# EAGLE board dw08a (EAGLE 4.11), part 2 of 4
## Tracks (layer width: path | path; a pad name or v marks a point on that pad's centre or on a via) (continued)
I_AC04  (via drill 0.61) (continued)
  Top 0.152: v105.28,40.39 105.28,35.94 105.92,35.31 105.92,30.86 B16.N2 | v109.98,49.28 110.62,48.64 v110.62,47.62 111,47.75 125.48,33.27 v125.98,33.27 | v119.38,60.33 121.41,62.36 v118.75,65.02 | v221.49,133.99 217.42,138.05 210.82,138.05 209.8,139.06 209.8,139.45 207.77,141.48 200.53,141.48 199.39,140.34 v199.01,140.08 | v232.54,141.86 233.17,141.86 v237.24,137.79 | v249.56,138.43 271.91,116.08 272.8,116.08 274.07,114.81 275.46,114.81 277.11,113.16 A03.J1 | v288.54,30.73 288.42,30.86 288.42,33.91 281.18,41.15 280.67,41.15 279.4,42.42 278.51,42.42 B03.J1 | v262.76,10.03 v267.59,10.03 | v256.67,4.32 246.51,4.32 v241.43,9.4 | v235.46,7.37 234.82,7.37 v229.87,12.32 | v226.69,9.14 224.79,9.14 208.53,25.4 207.14,25.4 206.63,25.91 203.84,25.91 199.64,30.1 197.61,30.1 v196.47,31.24 | v180.97,26.8 180.97,27.05 173.61,34.42 173.35,34.42 172.47,35.31 172.47,35.56 160.91,47.12 155.57,47.12 v149.22,53.47
  Bottom 0.152: v105.28,40.39 105.54,40.39 110.62,45.47 v110.62,47.62 | v109.98,49.28 109.98,50.93 v119.38,60.33 | v118.75,65.02 124.46,70.74 125.86,70.74 136.65,81.53 136.65,81.66 191.39,136.4 193.55,136.4 196.6,139.45 198.37,139.45 v199.01,140.08 | v221.49,133.99 221.49,134.24 229.11,141.86 v232.54,141.86 | v237.24,137.79 237.62,137.79 238.12,138.3 249.43,138.3 v249.56,138.43 | v288.54,30.73 288.29,30.73 v267.59,10.03 | v262.76,10.03 261.87,10.03 260.73,8.89 260.73,8.38 v256.67,4.32 | v241.43,9.4 241.3,9.4 239.27,7.37 v235.46,7.37 | v229.87,12.32 v226.69,9.14 | v196.47,31.24 188.09,31.24 187.07,30.23 184.4,30.23 v180.97,26.8 | v149.22,53.47 146.18,53.47 v125.98,33.27
I_AC05  (via drill 0.61)
  Top 0.152: v122.68,22.67 112.27,22.67 111.51,23.43 107.06,23.43 B16.R2 | v251.71,137.35 251.71,137.22 272.03,116.9 v272.16,116.9 | v272.16,114.36 272.16,113.6 275.72,110.05 275.72,108.9 277.5,107.12 A03.L1 | v278.38,33.97 278.13,34.23 278.13,35.75 B03.L1 | v263.65,19.24 260.1,19.24 v259.08,20.26 | v228.98,2.48 v240.41,2.48 | v226.44,1.46 220.09,1.46 219.58,0.95 217.93,0.95 210.19,8.7 209.42,8.7 208.91,9.21 208.28,9.21 175.13,42.35 175.13,43.62 174.62,44.13 173.23,44.13 v161.29,56.07
  Bottom 0.152: v122.68,22.67 147.19,47.18 153.03,47.18 161.93,56.07 | 161.93,56.07 168.53,62.67 168.53,63.31 182.75,77.53 182.75,77.66 188.47,83.38 188.72,83.38 220.73,115.38 221.23,115.38 235.97,130.11 236.47,130.11 242.44,136.08 250.44,136.08 v251.71,137.35 | v272.16,116.9 v272.16,114.36 | v278.38,33.97 278.38,32.83 274.7,29.15 273.56,29.15 v263.65,19.24 | v259.08,20.26 258.19,20.26 v240.41,2.48 | v228.98,2.48 227.46,2.48 v226.44,1.46 | 161.93,56.07 v161.29,56.07
I_AC06  (via drill 0.61)
  Top 0.152: v282.83,31.94 281.81,32.96 281.69,32.96 B03.M1 | v307.47,56.45 307.47,59.88 296.42,70.93 296.42,71.18 296.16,71.44 296.16,71.82 296.04,71.94 296.04,72.58 295.91,72.71 295.91,80.33 295.78,80.45 295.78,84.64 v287.27,93.15 | v294,100.52 292.1,100.52 289.69,102.93 | 289.69,102.93 v285.75,106.87 | v165.1,123.38 170.31,123.38 185.29,108.39 188.47,108.39 193.17,103.69 193.17,102.81 194.56,101.41 195.83,101.41 198.37,98.87 198.37,98.49 207.52,89.34 v207.52,89.22 | v263.52,134.81 265.05,134.81 280.04,119.83 280.04,118.43 282.07,116.39 282.07,113.09 289.31,105.86 289.31,105.6 289.69,105.22 289.69,102.93
  Bottom 0.152: v282.83,31.94 283.21,31.94 284.73,33.47 285.12,33.47 290.19,38.54 290.19,39.56 296.04,45.4 296.42,45.4 v307.47,56.45 | v287.27,93.15 287.27,93.79 v294,100.52 | v285.75,106.87 285.75,106.36 284.61,105.22 283.34,105.22 281.69,103.57 A03.M1 | v165.1,123.38 158.24,116.52 158.24,112.2 156.72,110.68 147.19,110.68 136.02,99.5 136.02,96.33 116.84,77.15 112.27,77.15 112.14,77.03 111.63,77.03 111.51,76.9 111.12,76.9 110.87,76.64 110.62,76.64 106.43,72.45 106.43,67.12 105.54,66.23 102.74,66.23 93.98,57.47 93.98,56.33 B17.D2 | v207.52,89.22 208.03,89.22 214.76,95.95 214.76,96.97 230.12,112.33 230.12,112.97 240.79,123.64 244.73,123.64 245.11,124.02 248.16,124.02 257.81,133.67 262.38,133.67 v263.52,134.81
I_AC07  (via drill 0.61)
  Top 0.152: v61.98,83.69 80.14,65.53 80.14,65.28 90.3,55.12 90.68,55.12 93.22,52.58 93.22,49.91 B17.F2 | v211.84,143 212.34,143 213.11,142.24 217.68,142.24 219.2,140.72 219.71,140.72 224.92,135.51 224.92,132.33 225.93,131.32 225.93,131.19 226.06,131.19 226.06,131.06 226.19,131.06 226.19,130.94 226.31,130.94 226.31,130.81 226.44,130.81 226.44,130.68 228.98,130.68 229.87,129.79 230.63,129.79 231.27,129.16 231.27,128.65 v231.78,128.14 | v267.72,138.18 v295.78,110.11 | v283.59,96.9 281.69,96.9 A03.P1 | v285.24,22.23 285.24,24.38 283.08,26.54 281.69,26.54 B03.P1 | v267.33,4.83 264.16,4.83 261.24,7.75 260.99,7.75 259.71,9.02 252.86,9.02 240.54,21.34 240.54,21.46 239.27,22.73 239.14,22.73 235.46,26.42 235.46,28.45 v234.7,29.21 | v243.97,38.1 243.46,38.1 243.08,38.48 242.57,38.48 242.44,38.61 242.32,38.61 242.32,38.73 242.19,38.73 242.19,38.86 242.06,38.86 242.06,38.99 241.94,38.99 241.94,39.12 241.81,39.12 241.81,39.24 239.27,41.78 239.14,41.78 239.14,41.91 239.01,41.91 239.01,42.04 238.89,42.04 238.89,42.16 238.76,42.16 238.76,42.29 238.63,42.29 238.63,42.42 236.09,44.96 235.97,44.96 235.97,45.09 235.84,45.09 235.84,45.21 235.71,45.21 235.71,45.34 235.59,45.34 235.59,45.47 235.46,45.47 235.46,45.59 232.92,48.13 232.79,48.13 232.79,48.26 232.66,48.26 232.66,48.39 232.54,48.39 232.54,48.51 232.41,48.51 232.41,48.64 232.28,48.64 232.28,48.77 229.74,51.31 229.62,51.31 229.62,51.44 229.49,51.44 229.49,51.56 229.36,51.56 229.36,51.69 229.24,51.69 229.24,51.82 229.11,51.82 229.11,55.12 224.41,59.82 221.74,59.82 221.36,60.2 217.81,60.2 v213.23,64.77
  Top 0.152: v200.03,54.48 200.03,54.99 190.63,64.39 190.63,65.28 188.59,67.31 188.21,67.31 171.96,83.57 171.96,84.84 v171.7,85.09 | v105.54,27.69 104.52,27.69 v87.76,44.45
  Bottom 0.152: v61.98,83.69 62.48,83.69 92.96,114.17 106.17,114.17 128.02,136.02 130.56,136.02 133.1,138.56 139.06,138.56 141.1,140.59 163.58,140.59 165.61,142.62 187.2,142.62 187.58,143 v211.84,143 | v231.78,128.14 231.78,128.65 233.81,130.68 233.93,130.68 237.36,134.11 239.4,134.11 242.06,136.78 246.25,136.78 247.14,137.67 250.95,137.67 251.46,138.18 v267.72,138.18 | v295.78,110.11 295.78,109.09 v283.59,96.9 | v285.24,22.23 284.73,22.23 v267.33,4.83 | v234.7,29.21 235.08,29.21 v243.97,38.1 | v213.23,64.77 213.23,64.64 204.98,56.39 204.6,56.39 203.71,55.5 203.2,55.5 202.18,54.48 v200.03,54.48 | v171.7,85.09 169.29,85.09 164.08,79.88 160.78,79.88 149.22,68.33 148.34,68.33 147.19,67.18 146.69,67.18 110.49,30.99 108.84,30.99 v105.54,27.69 | v87.76,44.45 87.76,44.96 89.92,47.12 91.31,47.12 92.96,48.77 B17.F2
I_AC08  (via drill 0.61)
  Top 0.152: v108.46,57.47 110.74,57.47 111.38,56.83 113.54,56.83 115.32,55.05 115.7,55.05 118.36,52.39 119.13,52.39 141.6,29.91 | 141.6,29.91 151.89,19.62 152.4,19.62 153.92,18.1 154.43,18.1 162.94,9.59 165.35,9.59 171.96,2.98 173.74,2.98 174.12,2.6 175.64,2.6 v176.78,1.46 | v206.38,25.08 208.28,25.08 221.74,11.62 221.74,10.35 224.79,7.3 227.71,7.3 v230.76,4.25 | v246.38,19.37 247.01,19.37 253.49,12.89 255.4,12.89 258.32,9.97 259.46,9.97 259.71,9.72 261.49,9.72 v264.41,6.79 | v256.29,113.6 271.91,97.98 275.08,97.98 280.67,92.39 280.67,91.25 A03.S1 | v254.89,112.33 254.38,112.33 252.86,113.86 252.6,113.86 252.22,114.24 252.22,114.75 229.74,137.22 229.11,137.22 v224.92,141.41 | v222.25,139.89 221.11,139.89 v219.46,141.54 | v196.85,117.79 196.85,115.89 211.71,101.03 v211.84,101.03 | 141.6,29.91 v141.73,29.91
  Bottom 0.152: v108.46,57.47 107.44,56.45 107.44,55.05 95.63,43.24 94.36,43.24 B17.J2 | v176.78,1.46 182.12,1.46 182.88,2.22 183.51,2.22 v206.38,25.08 | v230.76,4.25 231.01,4.25 237.11,10.35 237.36,10.35 v246.38,19.37 | v264.41,6.79 265.56,6.79 277.37,18.61 279.15,18.61 280.54,20 B03.S1 | v256.29,113.6 256.16,113.6 v254.89,112.33 | v224.92,141.41 223.77,141.41 v222.25,139.89 | v219.46,141.54 216.41,141.54 215.39,140.53 215.14,140.53 202.31,127.7 202.31,126.3 203.84,124.78 v196.85,117.79 | v211.84,101.03 211.84,100.27 207.65,96.08 207.01,96.08 199.14,88.2 199.14,86.68 189.48,77.03 188.85,77.03 v141.73,29.91
I_AC09  (via drill 0.61)
  Top 0.152: v275.34,49.4 272.29,52.45 272.29,53.59 271.91,53.98 271.91,54.86 B03.D2 | v257.43,31.5 257.43,29.84 v259.33,27.94 | v238.89,8.13 237.87,8.13 234.44,11.56 234.44,11.68 230.76,15.37 227.84,15.37 227.71,15.49 227.08,15.49 217.93,24.64 217.93,24.89 213.23,29.59 213.23,31.75 v213.11,31.88 | v213.23,33.91 212.72,33.91 210.95,35.69 210.44,35.69 208.53,37.59 v206.38,37.59 | v204.85,36.07 195.58,45.34 193.68,45.34 v192.91,44.58 | v169.8,25.53 v156.08,39.24 | v124.97,13.97 124.21,13.97 122.81,15.37 111.63,15.37 v94.11,32.89 | v262.25,132.08 268.48,125.86 270.76,125.86 A03.D2 | v244.47,114.81 244.47,115.32 243.97,115.82 243.97,116.46 243.84,116.46 243.84,116.59 243.71,116.59 243.71,116.71 243.59,116.71 243.59,116.84 243.46,116.84 243.46,116.97 243.33,116.97 240.79,119.51 240.79,119.63 240.66,119.63 240.66,119.76 240.54,119.76 240.54,119.89 240.41,119.89 240.41,120.02 240.28,120.02 240.28,120.14 240.16,120.14 237.62,122.68 237.62,122.81 237.49,122.81 237.49,122.94 237.36,122.94 237.36,123.06 237.24,123.06 237.24,123.19 237.11,123.19 237.11,123.32 236.98,123.32 235.84,124.46 235.84,124.59 233.93,126.49 231.78,126.49 230.89,127.38 228.22,127.38 225.43,130.18 222.63,130.18 222.12,130.68 220.09,130.68 214.63,136.14 212.98,136.14 211.58,137.54 210.57,137.54 v209.04,139.06 | v196.22,129.92 194.56,129.92 v193.55,130.94 | v152.91,93.09 152.91,89.92 162.94,79.88 165.99,79.88 167,78.87 167,76.2 170.43,72.77 170.43,72.39 201.04,41.78 203.2,41.78 v203.84,41.15
  Bottom 0.152: v257.43,31.5 v275.34,49.4 | v259.33,27.94 258.7,27.94 v238.89,8.13 | v213.11,31.88 213.11,33.78 v213.23,33.91 | v204.85,36.07 v206.38,37.59 206.63,37.97 207.01,38.35 207.01,39.12 204.98,41.15 v203.84,41.15 | v192.91,44.58 192.28,44.58 186.31,38.61 182.88,38.61 v169.8,25.53 | v156.08,39.24 150.5,33.66 150.5,33.4 146.94,29.84 146.94,29.59 131.7,14.35 130.18,14.35 127.76,16.76 v124.97,13.97 | v94.11,32.89 94.11,35.81 B17.L2 | v262.25,132.08 260.73,132.08 259.33,130.68 256.03,130.68 254.51,129.16 254.51,124.97 244.47,114.94 v244.47,114.81 | v209.04,139.06 207.26,139.06 200.53,132.33 200.53,131.7 199.52,130.68 196.98,130.68 v196.22,129.92 | v193.55,130.94 191.77,130.94 175.39,114.55 174.88,114.55 165.48,105.16 164.97,105.16 v152.91,93.09
I_AC10  (via drill 0.61)
  Top 0.152: v116.97,50.93 119.63,50.93 v151.76,18.8 | v186.69,17.02 174.62,29.08 169.29,29.08 167.89,30.48 167.51,30.48 166.88,31.11 v166.5,31.11 166.75,31.5 167.64,32.38 v168.78,32.38 | v197.87,24.89 198.37,24.89 200.91,22.35 201.42,22.35 210.57,13.21 215.14,13.21 216.03,12.32 217.81,12.32 v222.38,7.75 | v250.82,30.35 250.82,30.1 251.84,29.08 v253.87,29.08 | v253.24,139.95 270.51,122.68 273.94,122.68 A03.E2 | v217.55,119.51 217.55,119.25 v225.17,111.63 | v208.91,98.55 v211.96,98.55 | v194.56,83.57 194.82,83.57 196.72,81.66 196.72,80.64 v205.1,72.26 | v205.1,67.06 205.1,66.42 v206.38,65.15
  Bottom 0.152: v116.97,50.93 96.65,30.61 94.36,30.61 B17.N2 | v151.76,18.8 154.18,18.8 v166.5,31.11 | v186.69,17.02 186.82,17.02 194.69,24.89 v197.87,24.89 | v222.38,7.75 226.44,7.75 237.24,18.54 239.14,18.54 242.32,21.72 242.57,21.72 243.59,22.73 243.59,23.11 v250.82,30.35 | v253.87,29.08 261.75,36.96 261.87,36.96 262.38,37.47 262.38,37.97 268.35,43.94 268.35,44.45 272.54,48.64 272.54,50.04 274.19,51.69 B03.E2 | v253.24,139.95 249.3,139.95 246.13,143.13 239.52,143.13 236.73,140.34 236.73,139.83 224.41,127.51 223.27,127.51 222.88,127.13 222.88,124.84 v217.55,119.51 | v225.17,111.63 225.17,109.86 224.92,109.6 224.92,108.97 224.79,108.97 224.79,108.84 224.66,108.84 224.66,108.71 224.54,108.71 224.54,108.58 224.41,108.58 224.41,108.46 224.28,108.46 221.74,105.92 221.74,105.79 221.62,105.79 221.62,105.66 221.49,105.66 221.49,105.54 221.36,105.54 221.36,105.41 221.23,105.41 221.23,105.28 221.11,105.28 218.57,102.74 218.57,102.62 214.88,98.93 212.34,98.93 v211.96,98.55 | v208.91,98.55 198.75,88.39 198.75,87.76 v194.56,83.57 | v205.1,67.06 v205.1,72.26 | v206.38,65.15 206.38,65.02 205.36,64.01 202.69,64.01 202.56,63.88 201.17,63.88 186.94,49.66 186.06,49.66 v168.78,32.38
I_AC11  (via drill 0.61)
  Top 0.152: v101.6,17.21 101.09,17.72 101.09,17.97 95.63,23.43 94.36,23.43 B17.R2 | v205.49,111.82 206.5,111.82 v213.11,105.22 | v252.98,137.1 255.52,137.1 274.07,118.56 274.07,116.9 274.32,116.65 A03.H2 275.34,115.51 276.99,113.86 278.26,113.86 279.65,112.46 279.65,110.68 279.91,110.43 279.91,109.03 285.62,103.31 285.62,102.42 304.42,83.63 v304.42,82.61 | v281.05,38.04 274.95,44.13 274.95,45.28 B03.H2 | v289.94,46.93 289.94,46.29 294.13,42.1 294.77,42.1 298.7,38.16 298.7,36.89 v298.83,36.77 | v308.86,50.61 308.86,61.02 305.31,64.58 305.31,73.72 v304.42,74.61
  Bottom 0.152: v101.6,17.21 101.98,17.21 161.42,76.64 161.67,76.64 161.93,76.9 162.31,76.9 162.43,77.03 162.94,77.03 163.07,77.15 173.99,77.15 177.29,80.45 177.29,83.63 194.82,101.16 195.07,101.16 195.71,101.79 195.71,102.04 v205.49,111.82 | v213.11,105.22 214.76,105.22 217.93,108.39 219.07,108.39 229.24,118.56 230.5,118.56 233.81,121.86 234.06,121.86 239.14,126.94 242.82,126.94 v252.98,137.1 | v289.94,46.93 v281.05,38.04 | v298.83,36.77 299.72,36.77 300.36,37.4 300.36,37.91 304.67,42.23 304.67,46.42 v308.86,50.61 | v304.42,82.61 v304.42,74.61
I_ACCEPT  (via drill 0.61)
  Top 0.152: v241.05,7.18 227.97,20.26 224.54,20.26 B07.S2 223.14,21.02 222.63,21.53 | v259.84,22.42 260.1,22.42 261.37,21.14 B04.S2 | v144.53,66.74 144.53,66.61 156.72,54.42 162.05,54.42 v208.41,8.06 | v222.12,21.65 222.5,21.65 222.63,21.53 | v242.82,60.77 v236.85,66.74 | v216.41,31.56 222.63,25.34 222.63,21.53
  Bottom 0.152: v241.05,7.18 244.6,7.18 v259.84,22.42 | v144.53,66.74 134.87,57.09 134.37,57.09 132.84,55.56 132.84,55.05 130.05,52.26 130.05,51.75 124.71,46.42 122.94,46.42 B15.H2 | v208.41,8.06 208.53,8.06 v222.12,21.65 | v236.85,66.74 237.36,67.25 237.36,68.52 256.29,87.44 256.29,87.82 258.57,90.11 261.24,90.11 A04.S2 | v242.82,60.77 228.22,46.16 227.58,46.16 217.81,36.39 217.81,35.24 216.41,33.85 v216.41,31.56
I_ACCLR  (via drill 0.61)
  Top 0.152: v281.05,25.34 279.78,26.61 275.34,26.61 B03.P2 | v290.96,34.23 290.96,34.48 289.43,36.01 v289.43,38.92 | v303.78,53.91 303.28,53.91 292.61,64.58 292.61,68.64 v292.23,69.03 | v294.64,73.72 294.64,78.42 290.96,82.11 287.78,82.11 276.73,93.15 276.73,95.06 275.34,96.46 A03.P2 | v130.18,9.97 121.41,18.73 115.19,18.73 114.81,19.11 108.97,19.11 85.6,42.48 81.66,42.48 B18.J2 | v155.32,31.56 158.12,31.56 168.28,21.4 168.91,21.4 173.99,16.32 174.24,16.32 181.23,9.34 185.29,9.34 188.72,5.91 193.29,5.91 193.68,5.52 195.2,5.52 v197.99,2.73 | v215.9,9.08 218.82,9.08 v224.41,3.49 | v228.85,7.3 231.9,7.3 235.97,3.24 242.95,3.24 v243.46,2.73
  Bottom 0.152: 281.81,25.34 282.07,25.34 v290.96,34.23 | 281.81,25.34 v281.05,25.34 | v289.43,38.92 289.43,39.56 v303.78,53.91 | v292.23,69.03 292.23,71.31 v294.64,73.72 | v130.18,9.97 133.73,9.97 v155.32,31.56 | v197.99,2.73 208.53,2.73 208.79,2.98 209.8,2.98 v215.9,9.08 | v224.41,3.49 225.04,3.49 v228.85,7.3 | v243.46,2.73 259.21,2.73 281.81,25.34
I_ADD00  (via drill 0.61)
  Top 0.152: v71.75,37.78 55.88,53.66 55.88,54.8 B20.D2 | v146.81,99.25 148.97,99.25 v169.93,78.3 | v226.82,133.67 228.73,133.67 v246.51,115.89 246.76,115.51 v252.98,109.28 | v253.62,72.45 260.86,65.22 260.86,64.58 263.14,62.29 264.41,62.29 B04.B1 | v253.62,79.44 253.62,83.25 252.09,84.77 251.46,84.77 241.81,94.42 241.81,95.19 v240.16,96.84
  Bottom 0.152: v71.75,37.78 78.36,37.78 98.04,57.47 99.82,57.47 108.97,66.61 110.62,66.61 112.27,68.26 115.19,68.26 118.62,71.69 119.25,71.69 135.25,87.69 135.51,87.69 139.32,91.5 139.32,91.76 v146.81,99.25 | v169.93,78.3 174.5,82.87 175.13,82.87 192.15,99.89 192.15,100.52 194.56,102.93 195.33,102.93 205.99,113.6 206.76,113.6 v226.82,133.67 | v246.51,115.89 246.76,115.89 252.35,121.47 252.35,121.6 252.73,121.98 253.75,121.98 261.49,129.73 262.76,129.73 264.41,131.38 A04.B1 | v253.62,79.44 v253.62,72.45 | v240.16,96.84 240.54,96.84 v252.98,109.28
I_ADD01  (via drill 0.61)
  Top 0.152: v60.83,46.67 58.67,48.83 56.26,48.83 B20.F2 | v133.35,115.63 133.35,117.03 v135.38,119.06 | v136.53,120.21 139.95,120.21 141.6,118.56 142.88,118.56 143.89,117.54 148.46,117.54 158.12,107.89 159.51,107.89 v174.37,93.03 174.62,92.65 184.02,83.25 184.02,79.44 184.4,79.06 184.4,75.37 188.72,71.06 188.72,70.42 189.1,70.04 189.1,68.77 191.01,66.86 191.01,64.58 203.33,52.26 203.33,51.75 207.52,47.56 207.52,47.31 207.9,46.93 207.9,46.29 218.19,36.01 v218.57,36.01 | v224.03,142.3 225.3,142.3 v252.98,114.62 | v254,41.59 251.97,41.59 250.19,43.37 248.41,43.37 v240.03,51.75
  Bottom 0.152: v60.83,46.67 60.96,46.67 78.87,64.58 78.87,67.75 105.92,94.81 111.38,94.81 115.19,98.61 116.08,98.61 131.32,113.86 131.57,113.86 v133.35,115.63 | v136.53,120.21 v135.38,119.06 | v174.37,93.03 174.37,93.41 217.04,136.08 217.3,136.08 221.87,140.65 222.38,140.65 v224.03,142.3 | v252.98,114.62 252.98,115.25 256.03,118.3 256.41,118.3 261.49,123.38 262.76,123.38 264.41,125.03 A04.D1 | v254,41.59 264.8,52.39 264.8,54.8 B04.D1 | v240.03,51.75 239.4,51.75 228.6,40.96 226.69,40.96 224.28,38.54 221.11,38.54 v218.57,36.01
I_ADD02  (via drill 0.61)
  Top 0.152: v58.55,41.97 58.04,42.48 56.26,42.48 B20.J2 | v132.46,110.55 132.46,110.43 134.49,108.39 140.84,108.39 147.19,102.04 156.72,102.04 167.77,91 167.77,90.61 v168.28,90.11 | v221.62,141.41 222,141.41 227.71,135.7 227.71,135.19 240.79,122.11 241.43,122.11 v250.32,113.22 | v261.49,124.27 262.51,124.27 v266.06,120.71 | v257.56,64.45 258.95,63.06 259.21,63.06 267.08,55.18 267.08,54.42 267.97,53.53 267.97,53.15 B04.E1 | v258.06,69.15 258.06,69.91 249.05,78.93 v248.92,78.93 | v257.05,87.44 252.6,91.89 252.6,92.01 252.09,92.52 251.97,92.52 250.06,94.42 250.06,94.55 248.92,95.69 248.79,95.69 241.81,102.68 241.81,104.08 v241.43,104.46
  Bottom 0.152: v58.55,41.97 75.82,59.24 76.2,59.24 106.43,89.47 106.93,89.47 109.09,91.63 113.54,91.63 v132.46,110.55 | v168.28,90.11 170.31,90.11 v221.62,141.41 | v261.49,124.27 250.44,113.22 v250.32,113.22 249.94,112.97 v241.43,104.46 | v266.06,120.71 266.45,120.71 267.59,121.86 A04.E1 | v257.56,64.45 257.56,68.64 v258.06,69.15 | v248.92,78.93 248.92,79.57 255.02,85.66 255.27,85.66 v257.05,87.44
I_ADD03  (via drill 0.61)
  Top 0.152: v74.93,52.26 76.33,52.26 80.52,48.07 85.22,48.07 v101.35,31.94 | v186.31,113.73 186.31,113.22 210.57,88.96 211.07,88.96 212.85,87.19 212.85,86.17 217.3,81.72 218.31,81.72 220.22,79.82 222,79.82 222.5,79.31 | 222.5,79.31 v227.71,74.11 | v261.62,37.78 260.35,37.78 247.52,50.61 247.52,51.5 245.87,53.15 245.87,53.4 231.52,67.75 231.27,67.75 222.5,76.52 222.5,79.31
  Bottom 0.152: v74.93,52.26 59.56,36.89 56.26,36.89 B20.L2 | v101.35,31.94 109.73,31.94 110.62,32.83 110.62,36.01 121.79,47.18 124.97,47.18 129.67,51.88 129.67,55.05 140.84,66.23 142.88,66.23 144.15,67.5 146.94,67.5 148.08,68.64 148.97,68.64 151.26,70.93 151.26,71.18 151.51,71.44 151.51,71.82 151.64,71.94 151.64,72.58 151.76,72.71 151.76,79.18 171.32,98.74 171.96,98.74 184.91,111.7 184.91,112.33 v186.31,113.73 | v227.71,74.11 228.09,74.11 234.44,80.45 234.44,83.63 264.67,113.86 265.94,113.86 267.59,115.51 A04.H1 | v261.62,37.78 267.97,44.13 267.97,45.28 B04.H1
I_ADD04  (via drill 0.61)
  Top 0.152: v83.95,12.38 80.01,16.32 74.17,16.32 72.14,18.35 70.61,18.35 66.29,22.67 61.47,22.67 55.88,28.26 55.88,29.4 B20.N2 | v204.22,112.97 206.25,112.97 v206.38,112.84 | v228.35,132.91 228.98,132.91 230.89,131 230.89,130.62 244.73,116.78 244.73,116.39 v254.38,106.74 | v263.14,114.62 264.54,113.22 A04.J1 | v269.88,49.34 269.88,52.39 268.73,53.53 268.48,53.53 267.46,54.55 267.46,55.69 v258.83,64.33 | v260.86,71.31 260.22,71.31 259.46,72.07 259.46,72.71 259.08,73.09 259.08,78.3 252.22,85.15 251.59,85.15 246.89,89.85 246.89,90.49 v242.57,94.81
  Bottom 0.152: v83.95,12.38 92.84,12.38 96.27,15.81 96.77,15.81 99.57,18.61 102.87,18.61 161.29,77.03 161.54,77.03 161.8,77.28 162.18,77.28 162.31,77.41 162.81,77.41 162.94,77.53 168.02,77.53 169.54,79.06 170.18,79.06 174.37,83.25 175.01,83.25 191.77,100.01 191.77,100.65 194.44,103.31 194.69,103.31 204.22,112.84 v204.22,112.97 | v206.38,112.84 206.5,112.84 226.57,132.91 v228.35,132.91 | v263.14,114.62 255.27,106.74 v254.38,106.74 254.13,106.36 v242.57,94.81 | v269.88,49.34 265.43,44.9 265.43,43.62 B04.J1 | v258.83,64.33 258.83,69.28 v260.86,71.31
I_ADD05  (via drill 0.61)
  Top 0.152: v65.79,17.84 60.2,23.43 56.26,23.43 B20.R2 | v172.85,118.94 172.97,118.94 189.87,102.04 190.63,102.04 214.12,78.55 214.76,78.55 215.01,78.3 215.26,78.3 218.31,75.25 218.31,74.99 218.57,74.74 218.57,74.49 v219.07,73.98 239.4,53.66 239.4,53.53 v244.86,48.07 | v250.44,48.83 250.44,48.7 254.89,44.26 255.78,44.26 261.49,38.54 262.76,38.54 264.41,36.89 B04.L1 | v262.89,104.58 262.13,104.58 256.03,110.68 253.87,110.68 v253.62,110.93
  Bottom 0.152: v65.79,17.84 67.06,17.84 67.82,18.61 71.5,18.61 107.82,54.93 107.82,55.31 120.78,68.26 121.41,68.26 124.33,71.18 125.73,71.18 128.78,74.23 128.78,74.87 v172.85,118.94 | v244.86,48.07 246.51,48.07 247.27,48.83 v250.44,48.83 | v262.89,104.58 264.29,105.98 264.41,105.98 A04.L1 | v253.62,110.93 249.05,110.93 241.81,103.69 238.63,103.69 230.63,95.69 230.25,95.69 229.24,94.68 229.24,93.53 218.69,83 218.69,81.72 217.55,80.58 217.55,75.5 v219.07,73.98
I_ADD06  (via drill 0.61)
  Top 0.152: v295.53,68.9 295.53,71.69 293.88,73.34 293.88,73.72 v266.57,101.03 | v102.74,9.21 101.98,9.97 99.57,9.97 98.55,10.99 95.25,10.99 94.87,11.37 94.87,11.49 87.25,19.11 83.57,19.11 76.83,25.84 70.99,25.84 68.83,28 68.33,28 54.1,42.23 54.1,42.35 43.18,53.28 43.18,54.8 B21.D2 | v189.1,77.79 196.6,77.79 v197.1,77.28 | v227.58,103.57 227.58,103.31 236.35,94.55 237.24,94.55 245.62,86.17 247.52,86.17 v247.65,86.04
  Bottom 0.152: v295.53,68.9 295.15,68.52 295.15,64.45 294.77,64.07 294.77,58.23 270.26,33.72 268.99,33.72 B04.M1 | A04.M1 267.97,102.42 v266.57,101.03 266.19,101.16 264.67,101.16 263.02,99.5 262.38,99.5 248.92,86.04 v247.65,86.04 | v102.74,9.21 108.71,9.21 112.14,12.64 119,12.64 156.72,50.35 159.89,50.35 170.81,61.28 172.59,61.28 v189.1,77.79 | v197.1,77.28 197.1,77.79 197.99,78.68 202.69,78.68 v227.58,103.57
I_ADD07  (via drill 0.61)
  Top 0.152: v265.68,32.19 267.97,29.91 267.97,27.75 B04.P1 268.61,26.23 270.38,24.45 270.38,23.3 271.53,22.16 v271.53,21.4 | v285.37,52.64 285.37,52.77 273.56,64.58 273.56,66.99 v271.65,68.9 | v282.57,79.82 271.14,91.25 271.02,91.25 270.64,91.63 270.64,92.9 270.38,93.15 270.38,94.3 268.61,96.08 A04.P1 | v61.47,32.19 44.83,48.83 43.56,48.83 B21.F2 | v98.42,56.71 103.63,56.71 150.37,9.97 153.42,9.97 154.18,9.21 161.67,9.21 163.7,7.18 166.62,7.18 v167.64,6.16 | v175.01,12.26 177.8,12.26 181.1,8.95 185.17,8.95 v189.23,4.89 | v209.04,15.81 212.22,15.81 212.47,15.56 213.87,15.56 v216.28,13.14 | v224.92,21.91 230.5,21.91 241.94,10.48 241.94,10.35 v247.14,5.14
  Bottom 0.152: v265.68,32.19 265.68,33.21 267.59,35.12 267.84,35.12 v285.37,52.64 | v271.65,68.9 v282.57,79.82 | v61.47,32.19 73.91,32.19 v98.42,56.71 | v167.64,6.16 168.91,6.16 v175.01,12.26 | v189.23,4.89 198.12,4.89 v209.04,15.81 | v216.28,13.14 217.93,13.14 224.92,20.13 v224.92,21.91 | v247.14,5.14 255.27,5.14 v271.53,21.4
I_ADD08  (via drill 0.61)
  Top 0.152: v302.64,59.75 292.61,69.79 291.46,69.79 281.81,79.44 281.81,79.82 275.46,86.17 274.19,86.17 271.91,88.46 270.64,88.46 268.99,90.11 A04.S1 | v92.08,9.97 88.9,13.14 83.69,13.14 78.87,17.97 76.58,17.97 75.82,18.73 70.74,18.73 55.5,33.97 54.99,33.97 46.48,42.48 43.56,42.48 B21.J2 | v105.16,12.26 107.19,12.26 111.38,8.06 142.62,8.06 v144.78,5.91 | v194.44,52.26 195.07,52.26 203.2,44.13 205.49,44.13 v205.99,43.62 | v211.46,44.39 211.46,44.13 213.87,41.72 217.04,41.72 224.92,33.85 224.92,29.65 229.87,24.7 229.87,24.19 237.11,16.95 238.12,16.95 245.49,9.59 248.41,9.59 v248.79,9.21
  Bottom 0.152: v302.64,59.75 296.8,53.91 296.8,51.63 279.15,33.97 279.15,33.59 278.76,33.21 278.76,32.7 268.61,22.54 268.61,21.4 B04.S1 267.59,20.26 265.94,18.61 264.67,18.61 261.49,15.43 255.14,15.43 254.13,14.41 253.49,14.41 248.79,9.72 v248.79,9.21 | v92.08,9.97 101.47,9.97 101.85,10.35 103.25,10.35 v105.16,12.26 | v144.78,5.91 146.18,5.91 148.84,8.57 150.62,8.57 184.4,42.35 184.53,42.35 v194.44,52.26 | v205.99,43.62 207.14,43.62 207.52,44.01 211.07,44.01 v211.46,44.39
I_ADD09  (via drill 0.61)
  Top 0.152: v81.28,73.28 81.28,75.95 65.66,91.57 62.36,91.57 57.66,96.27 57.66,116.46 84.71,143.51 190.12,143.51 193.04,140.59 195.71,140.59 v210.82,125.48 | v228.85,143 229.62,143 v233.43,139.19 | v236.73,141.48 241.05,141.48 255.02,127.51 256.41,127.51 258.06,125.86 A04.D2 | v246.25,66.55 246.25,66.42 256.67,56.01 258.06,56.01 B04.D2 | v241.55,66.55 240.54,66.55 234.06,73.03 233.43,73.03 232.28,74.17 232.28,75.31 229.11,78.49 229.11,81.41 v220.22,90.3 | v221.74,92.08 221.74,94.23 203.45,112.52 v203.45,117.73
  Bottom 0.152: v81.28,73.28 44.96,36.96 43.56,36.96 B21.L2 | v228.85,143 219.58,133.73 219.58,133.22 213.23,126.87 211.84,126.87 210.82,125.86 v210.82,125.48 210.57,125.09 203.45,117.98 v203.45,117.73 | v233.43,139.19 234.44,139.19 v236.73,141.48 | v241.55,66.55 v246.25,66.55 | v220.22,90.3 220.22,90.55 v221.74,92.08
I_ADD10  (via drill 0.61)
  Top 0.152: v41.78,33.91 42.42,33.27 42.42,30.86 B21.N2 | v210.82,142.24 212.6,142.24 v213.74,141.1 | v227.58,143 227.71,143 v229.62,141.1 | v234.57,142.75 243.59,142.75 260.22,126.11 260.22,124.21 261.49,122.94 A04.E2 | v233.55,28.45 233.43,28.45 228.09,33.78 v228.09,33.91 | v224.16,30.48 224.03,30.48 v223.01,31.5 | v193.04,7.24 187.96,7.24 185.55,9.65 181.48,9.65 173.23,17.91 173.1,17.91 170.69,20.32 170.69,20.83 146.18,45.34 146.18,45.85 143.38,48.64 143.38,51.18 147.45,55.24 v134.37,68.33 | v134.37,72.77 134.37,72.9 v129.79,77.47 | v128.4,79.12 128.4,79.76 v106.43,101.73
  Bottom 0.152: v41.78,33.91 41.78,38.99 75.69,72.9 76.83,72.9 83.19,79.25 83.44,79.25 92.96,88.77 93.47,88.77 v106.43,101.73 108.97,104.27 114.81,104.27 134.24,123.7 138.94,123.7 145.8,130.56 147.45,130.56 153.42,136.53 164.08,136.53 166.5,138.94 183.51,138.94 183.9,139.32 190.12,139.32 193.04,142.24 v210.82,142.24 | v213.74,141.1 214.76,142.11 218.95,142.11 219.2,142.37 220.09,142.37 221.11,143.38 227.2,143.38 v227.58,143 | v229.62,141.1 232.92,141.1 v234.57,142.75 | v233.55,28.45 235.08,28.45 243.97,37.34 244.35,37.34 248.79,41.78 250.06,41.78 251.33,43.05 251.33,43.43 258.44,50.55 259.59,50.55 260.99,51.94 261.24,51.94 B04.E2 | v228.09,33.91 227.58,33.91 v224.16,30.48 | v223.01,31.5 223.01,30.99 221.74,29.72 221.74,29.59 221.62,29.59 221.62,29.46 221.49,29.46 221.49,29.34 221.36,29.34 221.36,29.21 221.23,29.21 221.23,29.08 221.11,29.08 218.57,26.54 218.57,26.42 218.44,26.42 218.44,26.29 218.31,26.29 218.31,26.16 218.19,26.16 218.19,26.04 218.06,26.04 218.06,25.91 217.93,25.91 215.39,23.37 215.39,23.24 215.26,23.24 215.26,23.11 215.14,23.11 215.14,22.99 215.01,22.99 215.01,22.86 214.88,22.86 214.88,22.73 214.76,22.73 212.22,20.19 212.22,20.07 212.09,20.07 212.09,19.94 211.96,19.94 211.96,19.81 211.84,19.81 211.84,19.68 211.71,19.68 211.71,19.56 211.58,19.56 209.04,17.02 209.04,16.89 208.53,16.38 206.76,16.38 206.25,15.88 203.71,15.88 199.01,11.18 196.98,11.18 v193.04,7.24 | v134.37,68.33 v134.37,72.77 | v129.79,77.47 128.27,78.99 v128.4,79.12
I_ADD11  (via drill 0.61)
  Top 0.152: v62.36,8.06 46.99,23.43 43.56,23.43 B21.R2 | v153.29,82.11 154.43,82.11 156.72,79.82 159.51,79.82 160.78,78.55 v166.24,78.55 | v191.01,100.39 191.77,100.39 214,78.17 214.63,78.17 214.88,77.92 215.14,77.92 217.93,75.12 217.93,74.87 218.19,74.61 218.19,74.23 218.31,74.11 218.31,73.6 v220.6,71.31 | v259.84,44.39 258.44,45.78 257.3,45.78 256.92,46.16 256.92,46.29 253.87,49.34 253.87,49.85 246.13,57.59 242.44,57.59 225.68,74.36 v225.68,74.49 225.43,74.87 223.39,76.9 v223.27,76.9
  Bottom 0.152: v62.36,8.06 76.33,8.06 150.37,82.11 v153.29,82.11 | v166.24,78.55 168.53,78.55 169.42,79.44 170.05,79.44 174.24,83.63 174.62,83.63 190.37,99.38 190.37,99.76 v191.01,100.39 | v220.6,71.31 222.5,71.31 v225.68,74.49 | v259.84,44.39 259.97,44.39 261.24,45.66 B04.H2 | v223.27,76.9 225.43,79.06 225.43,83.25 238.25,96.08 240.54,96.08 252.98,108.52 253.37,108.52 254.51,109.67 254.51,110.05 258.83,114.36 259.08,114.36 260.22,115.51 261.24,115.51 A04.H2
I_BAC00  (via drill 0.61)
  Top 0.152: v188.21,47.31 190.12,45.4 191.01,45.4 v198.75,37.66 | v224.79,63.69 224.92,63.69 226.31,62.29 B07.B1 | v307.34,67.37 307.34,74.36 v290.7,91 266.32,115.38 v265.68,115.38 | v233.81,76.01 233.81,76.77 v230.89,79.69
  Bottom 0.152: v188.21,47.31 187.32,46.42 186.44,46.42 B10.H2 | v198.75,37.66 v224.79,63.69 225.04,64.07 225.04,65.22 233.81,73.98 v233.81,76.01 | v307.34,67.37 306.2,66.23 305.94,66.23 303.53,63.82 303.53,62.67 B01.B1 | v290.7,91 290.7,91.38 301.75,102.42 301.75,116.01 304.29,118.56 304.29,130.24 303.53,131 A01.B1 | v230.89,79.69 230.89,80.58 v265.68,115.38
I_BAC01  (via drill 0.61)
  Top 0.152: v215.9,59.88 221.11,59.88 223.39,57.59 223.77,57.59 224.79,56.58 225.68,56.58 226.31,55.94 B07.D1 | v298.45,65.09 303.4,60.13 303.4,56.33 B01.D1 | v305.18,80.71 303.66,82.23 303.66,83.88 v283.72,103.82 283.34,104.08 275.72,111.7 v275.21,111.7 | v249.3,94.17 v251.84,91.63
  Bottom 0.152: B10.N2 183.26,30.54 186.82,30.54 214.88,58.61 214.88,58.86 v215.9,59.88 216.15,60.26 216.15,60.9 249.3,94.04 v249.3,94.17 | v298.45,65.09 298.45,65.72 303.66,70.93 303.66,71.18 303.91,71.44 303.91,71.82 304.04,71.94 304.04,72.58 304.17,72.71 304.17,73.22 305.18,74.23 v305.18,80.71 | v283.72,103.82 283.85,103.82 286.51,106.49 286.51,107.12 301.12,121.73 301.12,122.87 302.89,124.65 A01.D1 | v251.84,91.63 251.97,91.63 259.59,99.25 261.62,99.25 262.25,99.89 262.89,99.89 264.54,101.54 265.05,101.54 v275.21,111.7
I_BAC02  (via drill 0.61)
  Top 0.152: v304.55,68.26 304.93,67.88 304.93,64.45 308.48,60.9 308.48,56.33 306.7,54.55 306.7,53.15 B01.E1 | v309.75,88.84 309.75,118.43 306.7,121.47 A01.E1 | v257.68,57.85 256.79,58.74 256.79,59.12 256.03,59.88 v254.38,59.88 | v241.68,43.24 240.92,43.24 240.16,44.01 239.78,44.01 237.74,46.04 237.74,46.42 233.81,50.35 232.54,50.35 230.89,52.01 B07.E1
  Bottom 0.152: v304.55,68.26 304.55,68.9 306.2,70.55 306.2,71.06 307.85,72.71 307.85,84.64 308.23,85.03 308.23,87.31 v309.75,88.84 | B10.U2 186.44,14.67 188.47,14.67 196.34,22.54 198.12,22.54 224.03,48.45 224.66,48.45 226.57,50.35 227.84,50.35 229.49,52.01 B07.E1 | v257.68,57.85 263.65,63.82 264.67,63.82 266.45,65.6 266.45,65.85 285.12,84.52 285.12,85.53 286.64,87.06 287.91,87.06 305.31,104.46 305.31,116.39 306.07,117.16 306.07,121.47 A01.E1 | v254.38,59.88 254.38,56.45 254.13,56.2 254.13,53.15 253.24,52.26 253.24,51.63 251.33,49.72 251.33,48.58 250.82,48.07 247.01,48.07 246.63,47.69 246.13,47.69 v241.68,43.24
I_BAC03  (via drill 0.61)
  Top 0.152: v187.2,35.24 176.78,45.66 173.74,45.66 B11.H2 | v214.12,58.99 215.14,58.99 216.92,57.21 217.42,57.21 221.11,53.53 | 221.11,53.53 226.57,48.07 227.84,48.07 229.49,46.42 B07.H1 | v280.8,3.37 259.21,24.96 255.02,24.96 232.92,47.05 232.03,47.05 229.11,49.97 228.35,49.97 227.58,50.74 227.08,50.74 224.28,53.53 221.11,53.53 | v307.47,91.76 308.23,91.76 309.25,92.77 309.25,93.53 309.12,93.66 309.12,104.46 308.74,104.84 308.74,106.11 307.47,107.38 307.47,110.05 306.7,110.81 306.7,115.13 A01.H1 | v288.8,71.18 288.8,69.15 v289.43,68.52 | v286.51,66.74 287.15,66.74 287.65,66.23 287.78,66.23 292.86,61.15 293.37,61.15 302.01,52.51 302.01,52.01 304.29,49.72 304.29,48.58 306.07,46.8 B01.H1
  Bottom 0.152: v187.2,35.24 191.01,35.24 212.47,56.71 212.47,57.34 v214.12,58.99 | v280.8,3.37 281.18,3.75 285.24,3.75 309.12,27.62 309.12,38.54 306.7,40.96 306.7,45.28 B01.H1 | v307.47,91.76 307.47,89.98 306.83,89.34 306.32,89.34 305.44,88.46 305.44,87.82 v288.8,71.18 | v289.43,68.52 288.29,67.37 287.15,67.37 v286.51,66.74
I_BAC04  (via drill 0.61)
  Top 0.152: v184.15,43.12 186.31,43.12 v190.88,38.54 | v209.8,55.18 210.82,55.18 v224.92,41.08 | 284.61,69.79 284.1,70.29 284.1,71.82 v280.67,75.25 | 284.61,69.79 287.4,66.99 287.53,66.99 292.99,61.53 293.5,61.53 308.36,46.67 308.36,46.29 305.31,43.24 303.91,43.24 B01.J1 | v308.36,104.08 308.36,105.98 305.31,109.03 305.31,110.17 303.53,111.95 A01.J1 | v229.49,44.13 v233.93,39.69 | v249.81,55.56 249.81,54.93 253.62,51.12 254.38,51.12 v261.11,44.39 | v284.23,69.41 284.61,69.79
  Bottom 0.152: v184.15,43.12 183.64,42.61 183.64,42.35 171.83,30.54 170.56,30.54 B11.N2 | v190.88,38.54 193.29,38.54 209.8,55.05 v209.8,55.18 | v224.92,41.08 226.31,42.48 B07.J1 227.71,43.24 228.6,43.24 v229.49,44.13 | v280.67,75.25 280.67,75.37 291.97,86.68 291.97,86.93 293.75,88.71 293.75,88.96 307.47,102.68 307.47,103.19 v308.36,104.08 | v233.93,39.69 v249.81,55.56 | v261.11,44.39 261.87,44.39 269.37,51.88 269.37,52.26 271.14,54.04 271.53,54.04 272.54,55.05 272.54,57.72 273.56,58.74 273.56,59.24 280.54,66.23 281.05,66.23 v284.23,69.41
I_BAC05  (via drill 0.61)
  Top 0.152: v176.02,13.4 175.51,13.91 173.74,13.91 B11.U2 | v194.06,28.51 195.33,28.51 201.17,22.67 205.36,22.67 v208.28,19.75 | v274.07,68.14 v283.08,59.12 302.89,39.31 302.89,37.27 B01.L1 | v307.21,101.28 306.7,101.28 305.31,102.68 305.31,103.82 303.53,105.6 A01.L1 | v242.82,23.05 229.74,36.13 227.71,36.13 B07.L1
  Bottom 0.152: v176.02,13.4 176.91,13.4 191.64,28.13 193.68,28.13 v194.06,28.51 | v208.28,19.75 208.66,19.75 223.39,34.48 224.28,34.48 226.31,36.51 B07.L1 | v274.07,68.14 274.7,68.14 281.43,74.87 281.43,75.5 v307.21,101.28 | v242.82,23.05 242.82,23.43 269.49,50.1 270.76,50.1 277.37,56.71 280.67,56.71 v283.08,59.12
I_BAC06  (via drill 0.61)
  Top 0.152: 243.59,22.29 244.6,22.29 v246,20.89 | 243.59,22.29 242.44,22.29 240.79,23.94 240.79,24.32 232.16,32.96 230.89,32.96 B07.M1 | v251.21,22.29 251.84,22.29 256.67,17.46 257.18,17.46 261.49,13.14 267.84,13.14 v272.67,8.32 | v188.85,74.11 189.87,74.11 v195.83,68.14 | v198.75,68.14 199.01,68.14 243.59,23.56 243.59,22.29 | v305.05,92.65 305.05,91.25 304.04,90.23 v306.2,88.08 | v288.04,69.91 288.04,69.15 288.67,68.52 288.67,67.88 303.4,53.15 304.04,53.15 310.26,46.93 310.26,37.66 306.7,34.1 B01.M1
  Bottom 0.152: v246,20.89 247.9,20.89 248.79,21.78 250.7,21.78 v251.21,22.29 | v272.67,8.32 277.62,8.32 300.61,31.3 304.04,31.3 305.69,32.96 B01.M1 | v188.85,74.11 180.97,66.23 178.94,66.23 160.66,47.94 160.66,46.8 B12.H2 | v198.75,68.14 v195.83,68.14 | v305.05,92.65 305.31,92.9 305.31,97.35 310.39,102.42 310.39,103.19 308.74,104.84 307.98,104.84 306.96,103.82 306.96,103.69 A01.M1 | v306.2,88.08 306.2,87.44 289.18,70.42 288.54,70.42 v288.04,69.91
I_BAC07  (via drill 0.61)
  Top 0.152: v264.8,3.62 260.99,7.43 259.08,7.43 258.7,7.81 252.6,7.81 249.3,11.11 247.52,11.11 247.14,11.49 247.14,11.62 232.16,26.61 230.89,26.61 B07.P1 | v159.51,29.02 158.75,29.78 157.86,29.78 B12.N2 | v174.24,43.37 174.24,42.74 208.15,8.83 208.79,8.83 v209.68,7.94 | v287.02,69.03 287.02,67.88 287.53,67.37 288.16,67.37 308.74,46.8 308.74,37.27 303.28,31.81 304.29,30.8 304.29,29.53 306.07,27.75 B01.P1
  Bottom 0.152: v264.8,3.62 279.91,3.62 280.42,4.13 285.12,4.13 304.29,23.3 304.29,24.45 306.07,26.23 B01.P1 | v159.51,29.02 159.89,29.02 v174.24,43.37 | v209.68,7.94 209.68,8.06 226.57,24.96 227.84,24.96 229.49,26.61 B07.P1 | v287.02,69.03 287.15,69.15 288.42,69.15 307.47,88.2 307.47,88.84 310.39,91.76 310.39,92.39 306.7,96.08 A01.P1
I_BAC08  (via drill 0.61)
  Top 0.152: v180.72,31.56 184.02,31.56 195.58,20 195.58,19.75 v213.23,2.1 | B01.S1 306.07,19.88 306.07,18.73 288.29,0.95 249.3,0.95 246,4.25 245.36,4.25 244.86,4.76 244.6,4.76 239.4,9.97 239.27,9.97 232.28,16.95 232.28,18.1 230.5,19.88 B07.S1 | v308.23,88.46 306.83,89.85 A01.S1 | v309.5,46.55 v287.91,68.14
  Bottom 0.152: v180.72,31.56 163.83,14.67 161.04,14.67 B12.U2 | v213.23,2.1 214.63,3.49 215.14,3.49 228.47,16.83 228.47,17.46 229.24,18.22 229.24,19.24 229.87,19.88 B07.S1 | v287.91,68.14 v308.23,88.46 | v309.5,46.55 309.5,24.19 306.7,21.4 B01.S1
I_BAC09  (via drill 0.61)
  Top 0.152: v306.07,67.25 306.07,74.49 v298.45,82.11 | v307.47,93.92 307.47,99.89 306.45,100.9 306.45,101.03 304.93,102.55 304.93,103.06 302.13,105.86 302.13,111.7 301.75,112.08 301.75,118.94 298.96,121.73 298.96,122.87 297.18,124.65 A01.D2 | v164.85,32.89 152.15,45.59 148.34,45.59 B13.H2 | v166.88,34.92 168.78,34.92 v169.29,34.42 | v174.62,39.37 176.02,39.37 v180.47,34.92 | v193.8,43.69 194.94,44.83 v195.2,44.58 | v203.71,53.59 208.28,53.59 v212.09,49.78 | v229.36,136.4 228.85,136.4 221.87,143.38 213.87,143.38 v213.49,143 | v199.14,131.44 197.23,131.44 v196.85,131.83 | v121.16,63.88 121.79,63.88 128.02,57.66 131.19,57.66 132.21,56.64 132.33,56.64 132.33,56.52 132.46,56.52 132.46,56.39 132.59,56.39 132.59,56.26 132.72,56.26 132.72,56.13 132.84,56.13 132.84,50.8 v143.38,40.26
  Bottom 0.152: v306.07,67.25 297.18,58.36 297.18,56.33 B01.D2 | v298.45,82.11 298.45,84.26 304.04,89.85 304.04,90.49 v307.47,93.92 | v164.85,32.89 164.85,33.15 166.12,34.42 166.37,34.42 v166.88,34.92 | v169.29,34.42 169.67,34.42 v174.62,39.37 | v180.47,34.92 183.51,34.92 185.17,36.58 185.67,36.58 191.9,42.8 192.91,42.8 v193.8,43.69 | v195.2,44.58 195.2,45.09 v203.71,53.59 | v212.09,49.78 213.23,49.78 216.92,53.47 218.31,53.47 219.96,55.12 B07.D2 | v229.36,136.4 236.47,143.51 275.84,143.51 293.5,125.86 296.16,125.86 A01.D2 | v213.49,143 212.98,143 212.22,142.24 211.96,142.24 211.2,141.48 209.17,141.48 v199.14,131.44 | v196.85,131.83 195.2,133.48 194.94,133.48 194.56,133.1 193.42,133.1 175.39,115.06 174.88,115.06 165.35,105.54 164.85,105.54 159.38,100.08 158.88,100.08 157.73,98.93 154.43,98.93 137.03,81.53 137.03,81.15 124.97,69.09 124.59,69.09 121.16,65.66 v121.16,63.88 | v143.38,40.26 143.51,40.26 145.54,42.29 145.54,43.69 147.19,45.34 B13.H2
I_BAC10  (via drill 0.61)
  Top 0.152: v309.37,87.31 309.37,88.08 308.99,88.46 308.99,90.49 v308.48,91 | v308.48,93.15 308.48,102.81 307.59,103.69 307.59,106.24 304.93,108.9 304.93,109.41 302.13,112.2 302.13,119.7 300.36,121.47 A01.E2 | v172.09,4 172.09,4.13 148.08,28.13 147.96,28.13 146.3,29.78 145.16,29.78 B13.N2 | v296.04,52.01 299.34,52.01 B01.E2 | v259.97,21.14 258.32,21.14 232.79,46.67 231.9,46.67 228.98,49.59 228.22,49.59 227.46,50.35 226.19,50.35 224.54,52.01 B07.E2
  Bottom 0.152: v309.37,87.31 308.61,86.55 308.61,84.9 308.23,84.52 308.23,72.58 308.1,72.45 308.1,66.99 307.47,66.36 307.47,64.58 303.4,60.52 303.4,59.37 300.36,56.33 300.36,53.15 B01.E2 | v308.48,91 v308.48,93.15 | v172.09,4 173.86,4 185.29,15.43 188.72,15.43 196.22,22.92 197.1,22.92 207.52,33.34 207.52,33.97 215.77,42.23 215.77,42.74 221.74,48.7 221.74,49.85 223.52,51.63 B07.E2 | v296.04,52.01 296.04,51.88 281.43,37.27 280.16,37.27 265.56,22.67 261.49,22.67 v259.97,21.14
I_BAC11  (via drill 0.61)
  Top 0.152: v167.77,31.3 172.97,31.3 181.99,22.29 182.5,22.29 190.37,14.41 v190.5,14.41 | v296.42,44.64 296.42,44.9 287.78,53.53 287.02,53.53 v286.38,54.17 | v245.36,52.26 v264.67,32.96 | v232.16,39.18 232.16,39.81 227.58,44.39 225.81,44.39 224.54,45.66 B07.H2 | v284.61,127.06 292.48,119.19 292.86,119.19 295.78,116.27 299.34,116.27 A01.H2 | v244.73,95.69 242.44,95.69 238.63,99.5 238.63,103.19 229.74,112.08 229.74,112.33 v229.36,112.71 | v160.02,44.39 160.02,44.01 v168.02,36.01
  Bottom 0.152: v190.5,14.41 190.63,14.41 220.22,44.01 221.49,44.01 223.14,45.66 B07.H2 | B13.U2 148.34,14.67 151.13,14.67 v167.77,31.3 168.02,31.69 v168.02,36.01 | v296.42,44.64 297.43,45.66 299.34,45.66 B01.H2 | v286.38,54.17 285.75,54.17 264.67,33.08 v264.67,32.96 | v245.36,52.26 245.36,51.75 234.06,40.45 233.43,40.45 v232.16,39.18 | v284.61,127.06 276.1,127.06 264.92,115.89 264.92,115.25 263.52,113.86 262.89,113.86 v244.73,95.69 | v229.36,112.71 229.36,112.08 219.58,102.3 219.33,102.3 214.12,97.09 212.98,97.09 173.48,57.59 173.23,57.59 171.45,55.82 171.45,55.56 160.78,44.9 160.53,44.9 v160.02,44.39
I_BREAK  (via drill 0.61)
  Top 0.152: v242.7,10.86 230,23.56 228.73,23.56 228.35,23.94 228.35,24.07 225.81,26.61 224.54,26.61 B07.P2 | B23.V2 18.16,10.73 22.61,10.73 23.37,9.97 28.7,9.97 29.46,10.73 B22.V2 | v260.35,95.69 259.59,95.69 240.03,115.25 238.76,115.25 230.63,123.38 228.6,123.38 v228.35,123.64 | v204.22,101.03 204.22,101.28 v192.28,113.22 | v181.48,102.42 181.48,99.5 188.47,92.52 189.1,92.52 189.99,91.63 189.99,91 197.99,83 198.5,83 v199.26,82.23 | v221.87,24.96 215.65,31.18 215.65,31.56 v215.14,32.07 | v183.26,1.46 177.93,1.46 177.16,2.22 176.53,2.22 175.77,2.98 174.24,2.98 v147.7,29.53
  Bottom 0.152: v242.7,10.86 244.22,10.86 258.32,24.96 259.59,24.96 261.24,26.61 B04.P2 | 132.08,13.91 129.79,13.91 129.03,13.14 122.68,13.14 119.51,9.97 110.49,9.97 107.95,7.43 102.23,7.43 101.85,7.05 99.57,7.05 96.65,4.13 52.2,4.13 51.82,3.75 37.85,3.75 30.86,10.73 B22.V2 | 132.08,13.91 134.24,13.91 B14.U2 | v260.35,95.69 261.11,96.46 261.24,96.46 A04.P2 | v228.35,123.64 227.46,123.64 226.06,122.24 225.43,122.24 222.76,119.57 222.63,119.57 222.25,119.19 222.25,118.43 207.01,103.19 206.38,103.19 v204.22,101.03 | v181.48,102.42 v192.28,113.22 | v199.26,82.23 199.26,81.72 188.72,71.18 188.72,70.55 177.04,58.86 177.04,57.98 151.64,32.58 150.75,32.58 v147.7,29.53 132.08,13.91 | v221.87,24.96 223.27,26.35 223.39,26.35 B07.P2 | v215.14,32.07 214.5,32.07 206.76,24.32 206.12,24.32 v183.26,1.46
I_BRKRQ  (via drill 0.61)
  Top 0.152: v114.43,1.46 86.11,29.78 81.66,29.78 B18.N2 | v177.16,2.98 184.91,2.98 v186.18,1.71 | v228.09,18.73 228.35,18.73 v237.49,9.59 | B04.K2 262.64,39.31 264.29,37.66 265.56,37.66 267.08,36.13 265.81,34.86 v264.8,34.86 265.05,34.48 269.75,29.78 v269.88,29.78 | v283.46,91.5 264.41,110.55 263.78,109.92 262.64,109.92 A04.K2 | v269.62,76.52 269.62,74.87 285.62,58.86 285.62,57.72 v290.58,52.77
  Bottom 0.152: v114.43,1.46 169.16,1.46 169.67,0.95 175.13,0.95 v177.16,2.98 | v186.18,1.71 208.03,1.71 208.91,2.6 210.57,2.6 226.57,18.61 227.97,18.61 v228.09,18.73 | v237.49,9.59 239.78,9.59 263.02,32.83 263.02,33.08 v264.8,34.86 | v283.46,91.5 283.46,90.36 v269.62,76.52 | v290.58,52.77 290.58,50.86 283.08,43.37 283.08,42.99 281.31,41.21 280.92,41.21 270.38,30.67 270.38,30.29 v269.88,29.78
I_CAINCR  (via drill 0.61)
  Top 0.152: v70.74,44.01 75.95,44.01 111.51,8.45 143.38,8.45 148.21,3.62 159.77,3.62 161.04,2.35 168.28,2.35 169.42,1.21 174.24,1.21 v174.88,1.84 | v192.66,17.59 193.55,17.59 v209.3,1.84 | v252.86,98.36 252.35,98.87 251.97,98.87 249.56,101.28 249.56,102.42 A05.M2 | v212.72,61.91 217.04,57.59 222.88,57.59 242.32,38.16 242.82,38.16 245.62,35.37 246.89,35.37 248.54,33.72 B05.M2
  Bottom 0.152: v70.74,44.01 69.98,43.24 68.96,43.24 B19.J2 | v174.88,1.84 176.78,3.75 178.56,3.75 189.99,15.18 190.25,15.18 v192.66,17.59 | v209.3,1.84 211.84,1.84 212.85,2.86 213.49,2.86 214.5,3.87 215.01,3.87 228.09,16.95 228.09,17.59 228.85,18.35 228.85,20.89 229.74,21.78 232.92,21.78 240.54,29.4 241.68,29.4 243.08,30.8 244.6,30.8 248.67,34.86 249.17,34.86 251.97,37.66 252.86,37.66 254,36.51 252.86,35.37 251.59,35.37 249.94,33.72 B05.M2 | v252.86,98.36 252.35,98.36 248.54,94.55 248.54,93.79 227.84,73.09 225.93,73.09 223.9,71.06 223.9,70.42 220.34,66.86 217.68,66.86 v212.72,61.91
I_DATA00  (via drill 0.61)
  Top 0.152: v82.3,18.73 81.92,19.11 70.87,19.11 34.8,55.18 30.86,55.18 B22.D2 | v174.88,107.76 178.82,107.76 v185.93,100.65 186.31,100.39 192.91,93.79 192.91,93.41 197.74,88.58 200.28,88.58 200.41,88.46 202.06,88.46 204.85,85.66 205.36,85.66 v211.71,79.31 | v215.01,123.13 223.39,114.75 227.08,114.75 227.84,113.98 228.98,113.98 229.74,114.75 v230.25,114.24 | v240.16,53.91 239.78,53.91 229.11,64.58 229.11,65.09 215.52,78.68 215.14,78.68 v214.5,79.31
  Bottom 0.152: v82.3,18.73 85.85,18.73 v174.88,107.76 | v185.93,100.65 194.44,109.16 195.45,109.16 196.72,110.43 196.72,111.44 200.41,115.13 201.93,115.13 204.22,117.41 204.72,117.41 207.52,120.21 212.09,120.21 v215.01,123.13 | v230.25,114.24 230.89,114.24 240.66,124.02 241.43,124.02 245.24,127.83 246.89,127.83 248.79,129.73 250.06,129.73 251.71,131.38 A05.B1 | v240.16,53.91 243.84,57.59 249.68,57.59 252.09,60.01 252.09,61.15 B05.B1 | v211.71,79.31 v214.5,79.31
I_DATA01  (via drill 0.61)
  Top 0.152: v128.65,130.75 131.19,130.75 131.32,130.62 141.99,130.62 142.24,130.37 142.62,130.37 174.12,98.87 174.12,98.23 183.77,88.58 186.06,88.58 191.64,83 193.93,83 194.18,82.74 195.07,82.74 196.34,81.47 196.34,79.95 v198.37,77.92 | v232.41,45.91 v236.85,41.47 | v228.22,41.72 225.93,41.72 208.03,59.63 208.03,60.26 203.71,64.58 203.71,68.64 203.2,69.15 v203.2,73.09
  Bottom 0.152: v128.65,130.75 102.23,104.33 96.39,104.33 85.22,93.15 85.22,89.98 63.25,68.01 63.25,66.99 46.61,50.35 36.07,50.35 35.31,49.59 30.86,49.59 B22.F2 | 202.44,77.92 206.5,77.92 250.32,121.73 250.32,122.87 252.09,124.65 A05.D1 | v198.37,77.92 202.44,77.92 | v236.85,41.47 238.25,42.86 238.25,43.5 249.56,54.8 250.19,54.8 250.57,55.18 251.71,55.18 B05.D1 | v228.22,41.72 v232.41,45.91 | v203.2,73.09 202.44,73.85 202.44,77.92
I_DATA02  (via drill 0.61)
  Top 0.152: v25.53,51.18 29.72,46.99 29.72,43.56 B22.J2 | v132.08,140.59 192.02,140.59 192.79,139.83 194.18,139.83 v196.47,137.54 | v200.53,138.3 203.33,138.3 v206.38,135.25 | v210.82,139.32 216.28,139.32 v216.66,138.94 | v221.49,142.62 228.09,136.02 228.09,135.38 232.79,130.68 233.43,130.68 v234.19,129.92 | v238.12,133.35 242.19,133.35 249.43,126.11 250.06,126.11 251.84,124.33 253.24,124.33 254.89,122.68 A05.E1 | v251.59,57.15 252.09,56.64 252.98,56.64 252.98,56.52 253.11,56.52 253.11,56.39 253.24,56.39 253.24,56.26 253.37,56.26 253.37,56.13 253.49,56.13 253.49,56.01 255.14,54.36 255.14,53.09 B05.E1 | v238.63,46.48 238.25,46.48 224.54,60.2 221.87,60.2 221.49,60.58 219.71,60.58 216.79,63.5 216.28,63.5 190.37,89.41 189.48,89.41 v181.48,97.41 | v187.32,103.12 187.32,103.5 v175.01,115.82
  Bottom 0.152: v25.53,51.18 25.53,58.93 40.39,73.79 41.02,73.79 41.53,73.28 41.53,65.28 41.15,64.9 41.15,64.14 42.04,63.25 52.07,73.28 52.07,79.63 92.96,120.52 93.47,120.52 96.27,123.32 102.62,123.32 108.97,129.67 121.16,129.67 v132.08,140.59 | v200.53,138.3 199.77,137.54 v196.47,137.54 196.22,137.16 175.01,115.95 v175.01,115.82 | v206.38,135.25 206.76,135.25 v210.82,139.32 | v216.66,138.94 217.93,138.94 221.49,142.49 v221.49,142.62 | v234.19,129.92 234.7,129.92 v238.12,133.35 | v251.59,57.15 250.06,57.15 248.92,56.01 248.16,56.01 245.24,53.09 245.11,53.09 243.97,51.94 243.97,51.82 v238.63,46.48 | v181.48,97.41 181.61,97.41 v187.32,103.12
I_DATA03  (via drill 0.61)
  Top 0.152: v98.04,105.16 v98.04,100.58 | v107.95,112.65 107.95,122.17 105.28,124.84 105.28,125.98 122.43,143.13 189.99,143.13 192.91,140.21 194.94,140.21 v200.79,134.37 v203.2,131.95 | v209.8,137.16 211.46,137.16 214.12,134.49 214.5,134.49 220.47,128.52 221.87,128.52 v223.65,126.75 | v237.49,139.7 239.78,139.7 256.67,122.81 256.67,119.51 261.37,114.81 261.62,114.81 262.13,114.3 262.13,113.54 261.37,112.78 258.44,115.7 256.29,115.7 A05.H1 | v244.98,56.77 244.98,54.99 246.51,53.47 249.81,53.47 249.81,53.34 249.94,53.34 249.94,53.21 250.06,53.21 250.06,53.09 250.19,53.09 250.19,52.96 250.32,52.96 250.32,52.83 252.86,50.29 252.98,50.29 252.98,50.16 253.11,50.16 253.11,50.04 253.24,50.04 253.24,49.91 253.37,49.91 253.37,49.78 253.49,49.78 253.49,49.15 255.14,47.5 255.14,46.74 B05.H1 | v248.54,56.77 248.54,57.78 248.16,58.17 248.16,59.31 249.17,60.33 248.28,61.21 248.28,61.85 245.11,65.02 244.6,65.02 v238.63,70.99 | v225.93,60.33 v228.6,57.66 | v221.49,70.48 v226.69,65.28 | v228.09,79.38 228.09,81.53 227.58,82.04 224.41,82.04 223.39,83.06 223.27,83.06 223.27,83.19 223.14,83.19 223.14,83.31 223.01,83.31 223.01,83.44 222.88,83.44 222.88,83.57 222.76,83.57 222.76,84.84 223.77,85.85 221.23,88.39 220.98,88.39 219.46,89.92 219.46,90.68 214.63,95.5 213.74,95.5 213.23,96.01 213.23,97.28 212.98,97.54 212.98,98.68 212.34,99.31 210.44,99.31 v200.03,109.73 | v180.47,98.42 v175.13,103.76
  Bottom 0.152: v98.04,100.58 34.42,36.96 30.86,36.96 B22.L2 | v98.04,105.16 100.46,105.16 v107.95,112.65 | v203.2,131.95 203.45,131.95 205.74,134.24 206.88,134.24 v209.8,137.16 | v223.65,126.75 224.54,126.75 v237.49,139.7 | v248.54,56.77 v244.98,56.77 | v238.63,70.99 238.63,70.36 236.98,68.71 236.98,67.94 236.09,67.06 236.09,66.17 235.97,66.17 235.97,66.04 235.84,66.04 235.84,65.91 235.71,65.91 235.71,65.79 235.59,65.79 235.59,65.66 235.46,65.66 235.46,62.99 234.57,62.1 234.57,61.47 230.76,57.66 v228.6,57.66 | v225.93,60.33 225.93,64.52 v226.69,65.28 | v221.49,70.48 220.22,70.48 219.46,71.25 220.34,72.14 220.85,72.14 v228.09,79.38 | v200.03,109.73 200.03,109.47 192.66,102.11 191.64,102.11 190.25,100.71 190.25,100.2 189.99,99.95 189.99,99.44 189.87,99.44 189.87,99.31 189.74,99.31 189.74,99.19 189.61,99.19 189.61,99.06 189.48,99.06 189.48,98.93 189.36,98.93 186.82,96.39 186.82,96.27 186.69,96.27 186.69,96.14 186.56,96.14 186.56,96.01 186.44,96.01 186.44,95.89 186.31,95.89 186.31,95.76 182.12,95.76 175.9,89.53 175.26,89.53 174.5,90.3 180.47,96.27 v180.47,98.42 | v175.13,103.76 175.26,103.76 183.64,112.14 183.64,113.67 184.02,114.05 184.02,115.7 184.4,116.08 184.4,117.47 186.94,120.02 186.94,121.79 195.83,130.68 196.47,130.68 196.85,131.06 197.49,131.06 v200.79,134.37
I_DATA04  (via drill 0.61)
  Top 0.152: v55.88,2.86 30.48,28.26 30.48,29.4 B22.N2 | v190.5,23.69 191.39,23.69 195.2,19.88 195.2,19.62 203.07,11.75 203.07,11.11 v207.01,7.18 | v254.25,114.62 254.13,114.62 v245.49,123.25 | v204.85,82.49 204.85,76.52 v206.12,75.25 | v186.31,50.74 186.31,48.07 197.1,37.27 197.23,37.27 197.61,36.89 197.61,34.86 v197.23,34.48
  Bottom 0.152: v55.88,2.86 169.67,2.86 v190.5,23.69 190.75,24.07 197.23,30.54 v197.23,34.48 | v207.01,7.18 211.71,7.18 213.74,9.21 214.88,9.21 215.52,9.84 217.3,9.84 229.62,22.16 230.12,22.16 239.27,31.3 242.44,31.3 250.32,39.18 250.32,40.32 252.09,42.1 B05.J1 | v254.25,114.62 252.98,113.35 252.98,113.22 A05.J1 | v245.49,123.25 243.33,121.09 240.16,121.09 225.93,106.87 225.93,103.57 v204.85,82.49 | v206.12,75.25 206.12,74.36 197.36,65.6 197.36,61.28 190.88,54.8 190.37,54.8 v186.31,50.74
I_DATA05  (via drill 0.61)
